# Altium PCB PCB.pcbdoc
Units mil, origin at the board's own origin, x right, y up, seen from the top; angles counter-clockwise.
Board outline 5096.34 x 3724.82 mil, 2 copper layers (Top Layer, Bottom Layer); 10 components, 40 nets, 79 pads, 2 vias.
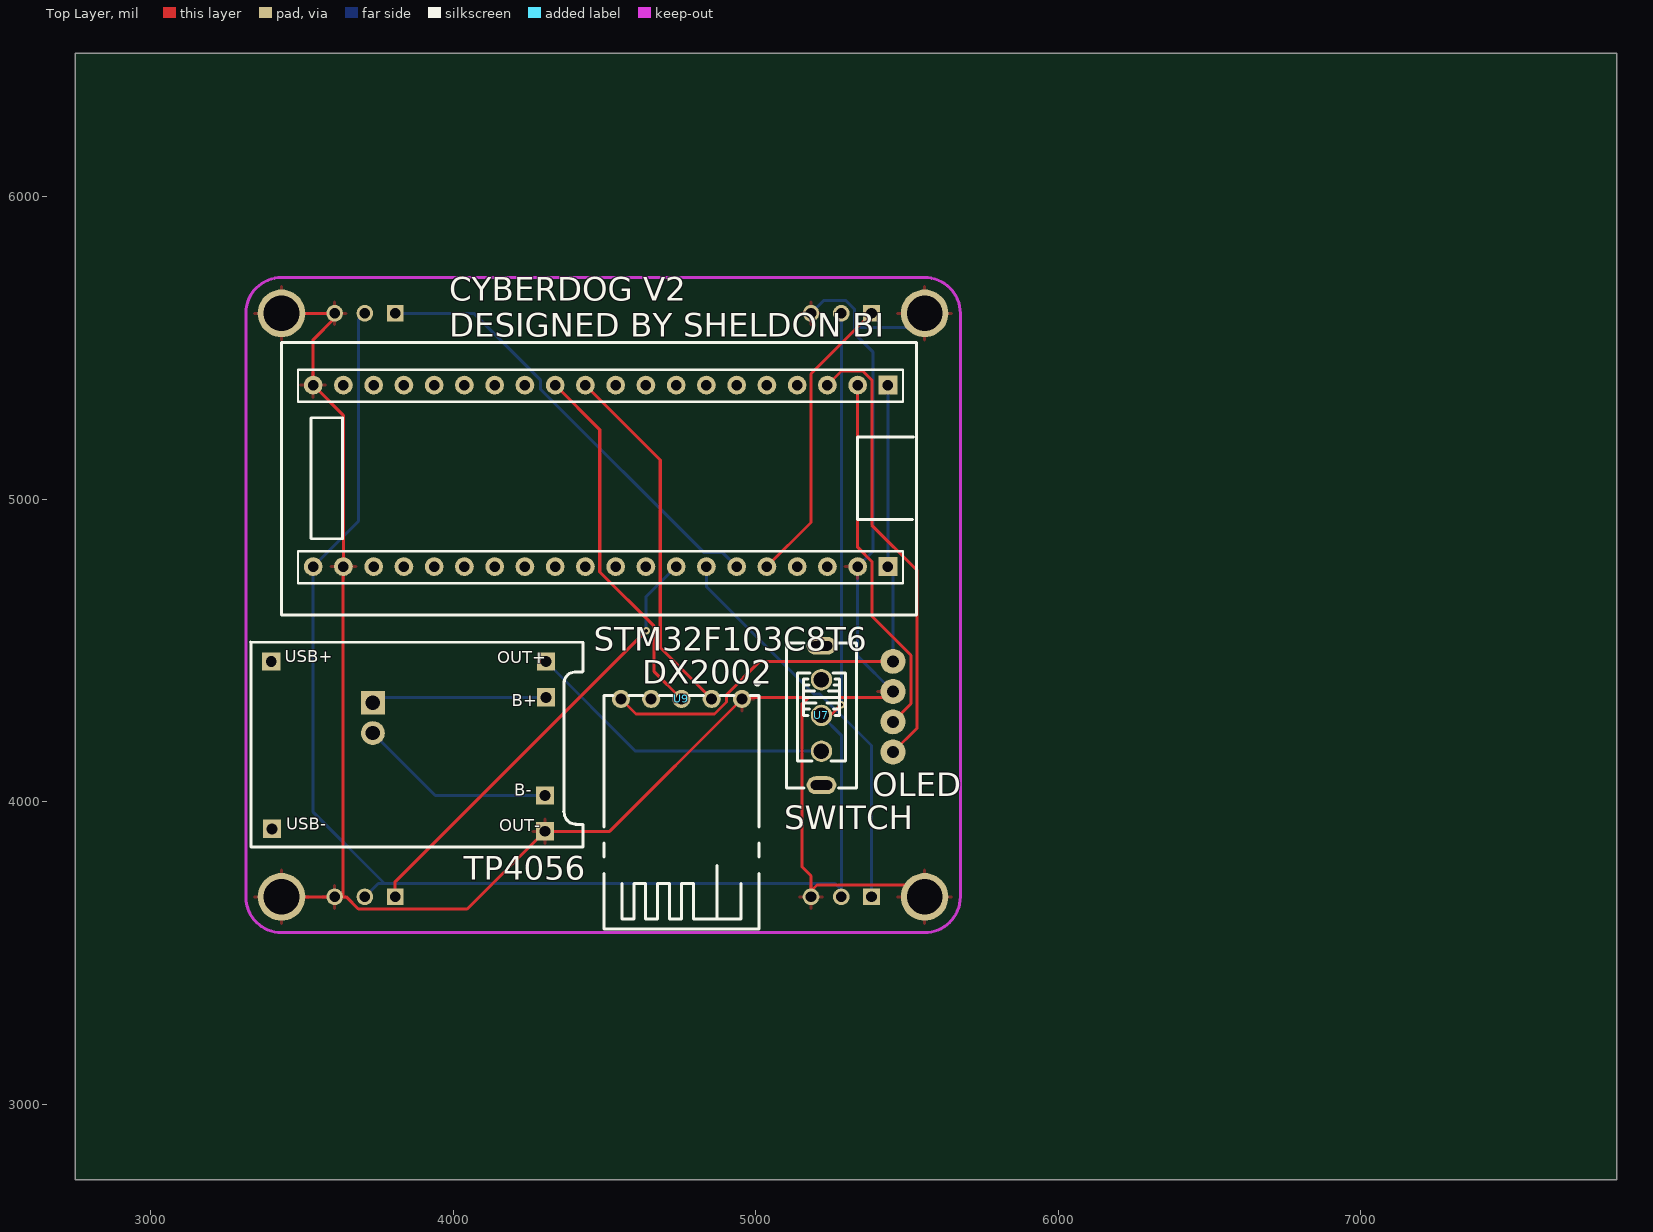
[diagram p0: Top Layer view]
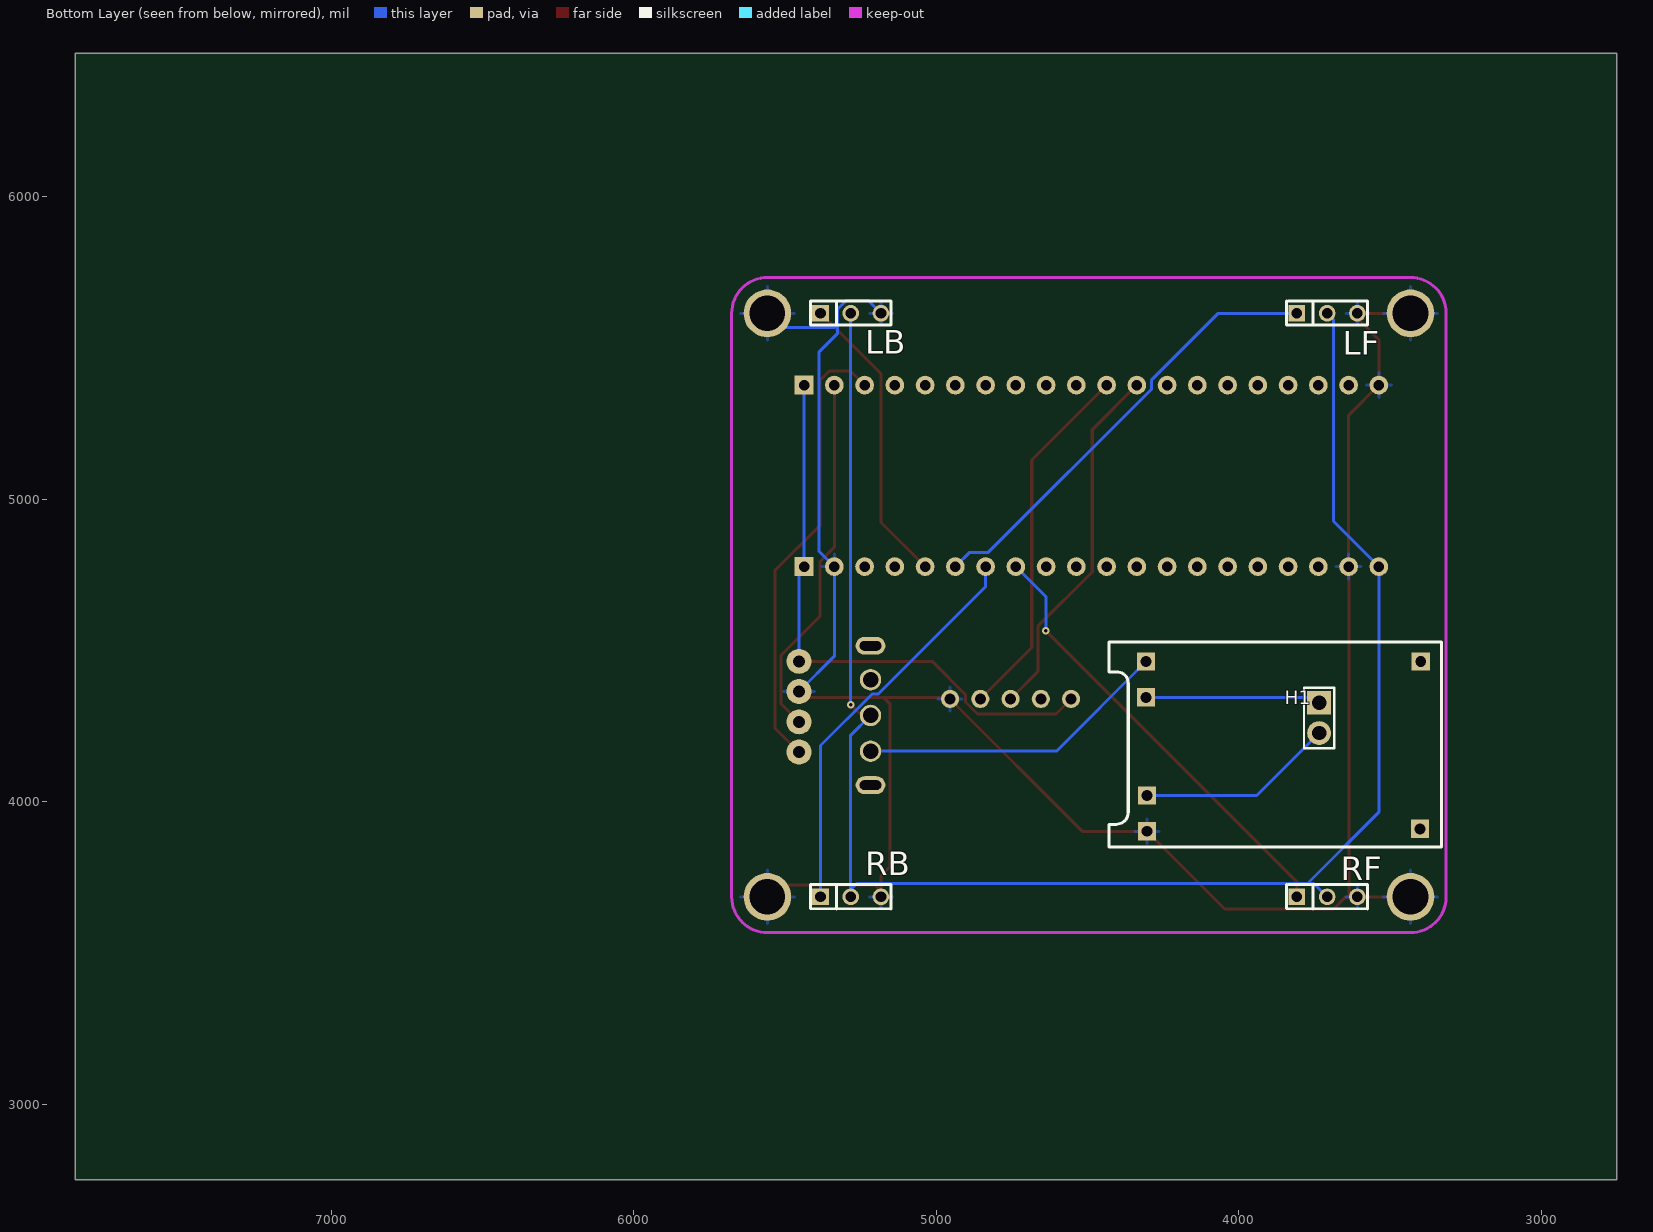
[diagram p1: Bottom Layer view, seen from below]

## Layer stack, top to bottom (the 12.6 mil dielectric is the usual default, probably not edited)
Top Layer: signal copper (thickness not stored)
Dielectric: dielectric 12.6, FR-4, Dk 4.8
Bottom Layer: signal copper (thickness not stored)

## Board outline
7846.34,2750 2750,2750 2750,6474.82 7846.34,6474.82

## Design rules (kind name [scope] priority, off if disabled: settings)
BoardOutlineClearance copperThickness1oz [All] p0: genericclearance=10 ignorepadtopadclearanceinfootprint=FALSE except(0: Arc-SplitContinuation Track-SplitContinuation SMDPad-SplitContinuation THPad-SplitContinuation Via-SplitContinuation Fill-SplitContinuation Poly-SplitContinuation Region-SplitContinuation Text-SplitContinuation; 6: SMDPad-CutoutEdge THPad-CutoutEdge Via-CutoutEdge Fill-CutoutEdge Region-CutoutEdge; 11.8: Track-OutlineEdge SMDPad-OutlineEdge THPad-OutlineEdge Via-OutlineEdge Fill-OutlineEdge Region-OutlineEdge Poly-OutlineEdge Text-OutlineEdge Track-CutoutEdge)
BoardOutlineClearance copperThickness2oz [All] p0: genericclearance=10 ignorepadtopadclearanceinfootprint=FALSE except(0: Arc-SplitContinuation Track-SplitContinuation SMDPad-SplitContinuation THPad-SplitContinuation Via-SplitContinuation Fill-SplitContinuation Poly-SplitContinuation Region-SplitContinuation Text-SplitContinuation; 6: SMDPad-CutoutEdge THPad-CutoutEdge Via-CutoutEdge Fill-CutoutEdge Region-CutoutEdge; 11.8: Track-OutlineEdge SMDPad-OutlineEdge THPad-OutlineEdge Via-OutlineEdge Fill-OutlineEdge Region-OutlineEdge Poly-OutlineEdge Text-OutlineEdge Track-CutoutEdge)
Clearance copperThickness1oz [(InNet('+5V') OR InNet('PA0') OR InNet('PA2') OR InNet('PA3') OR InNet('PA6') OR InNet('VCC') OR InNet('GND') OR InNet('PB9') OR InNet('PB8') OR InNet('PB7') OR InNet('PA15') OR InNet('BLUE_RX') OR InNet('PA8') OR InNet('K4') OR InNet('K3') OR InNet('K2') OR InNet('K1') OR InNet('BLUE_TX') OR InNet('BV-') OR InNet('PB4') OR InNet('PB3') OR InNet('B+5V') OR InNet('BV+') OR InNet('PA7') OR InNet('PB0') OR InNet('PB1') OR InNet('PB6') OR InNet('PB5') OR InNet('PA1') OR InNet('PA4') OR InNet('PA5') OR InNet('PB10') OR InNet('PB11') OR InNet('PA12') OR InNet('PA11') OR InNet('$1N16952') OR InNet('PB2') OR InNet('$1N16963') OR InNet('PA14') OR InNet('PA13'))] p1: gap=7 ignorepadtopadclearanceinfootprint=FALSE except(4: Track-Track; 6: Track-SMDPad SMDPad-SMDPad Track-THPad SMDPad-THPad THPad-THPad Track-Via SMDPad-Via THPad-Via Via-Via Track-Fill SMDPad-Fill THPad-Fill Via-Fill Fill-Fill SMDPad-Region THPad-Region Via-Region Fill-Region Region-Region Track-Poly SMDPad-Poly THPad-Poly Via-Poly Fill-Poly Poly-Poly Track-Text SMDPad-Text THPad-Text Via-Text Fill-Text Region-Text Poly-Text Text-Text Track-Hole SMDPad-Hole THPad-Hole Via-Hole Fill-Hole Region-Hole Poly-Hole Text-Hole; 11.8: Track-Region Region-Poly Track-Sheet SMDPad-Sheet THPad-Sheet Via-Sheet Fill-Sheet Region-Sheet Poly-Sheet Text-Sheet Sheet-Hole)
Clearance copperThickness2oz [All] p1: gap=7 ignorepadtopadclearanceinfootprint=FALSE except(6: Track-SMDPad SMDPad-SMDPad Track-THPad SMDPad-THPad THPad-THPad Track-Via SMDPad-Via THPad-Via Via-Via Track-Fill SMDPad-Fill THPad-Fill Via-Fill Fill-Fill SMDPad-Region THPad-Region Via-Region Fill-Region Region-Region Track-Poly SMDPad-Poly THPad-Poly Via-Poly Fill-Poly Poly-Poly Track-Text SMDPad-Text THPad-Text Via-Text Fill-Text Region-Text Poly-Text Text-Text Track-Hole SMDPad-Hole THPad-Hole Via-Hole Fill-Hole Region-Hole Poly-Hole Text-Hole; 8: Track-Track; 11.8: Track-Region Region-Poly Track-Sheet SMDPad-Sheet THPad-Sheet Via-Sheet Fill-Sheet Region-Sheet Poly-Sheet Text-Sheet Sheet-Hole)
DiffPairsRouting differentialPair [All] p1: maxuncoupledlength=10 minlimit=6 maxlimit=6 mostfreqgap=6 toplayer_minwidth=5 toplayer_prefwidth=10 toplayer_maxwidth=100 bottomlayer_minwidth=5 bottomlayer_prefwidth=10 bottomlayer_maxwidth=100
PasteMaskExpansion pasteMaskExpansion [All] p1: expansion=0
PlaneConnect innerPlane [All] p1: planeconnectstyle=Relief reliefexpansion=20 reliefentries=4 reliefconductorwidth=10 reliefairgap=10
PolygonConnect copperRegion [All] p1: connectstyle=Relief reliefentries=4 reliefconductorwidth=10 polygonreliefangle="90 Angle" airgapwidth=10
RoutingVias viaSize [All] p1: viastyle="Through Hole" holewidth=12.0078 minholewidth=11.811 maxholewidth=248.0314 width=24.0158 minwidth=19.685 maxwidth=393.7008
SolderMaskExpansion solderMaskExpansion [All] p1: useseparateexpansions=TRUE expansion=2 expansionbottom=2
Width copperThickness1oz [All] p1: maxlimit=100 minlimit=5 preferedwidth=10
Width copperThickness2oz [All] p1: maxlimit=100 minlimit=8 preferedwidth=10

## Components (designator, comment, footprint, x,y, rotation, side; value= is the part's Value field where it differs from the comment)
H1 "PZ254V-11-02P" HDR-TH_2P-P2.54-V-M 3734.15,4277.19 r270 bottom
LB "3pin插件排针" HDR-TH_3P-P2.54-V-M 5282.52,5614.94 r180 bottom
LF "3pin插件排针" HDR-TH_3P-P2.54-V-M 3707.72,5614.94 r180 bottom
OLED "OLED" "oled 1.3寸" 5453.36,4314.34 r270 top
RB "3pin插件排针" HDR-TH_3P-P2.54-V-M 5282.52,3685.81 r180 bottom
RF "3pin插件排针" HDR-TH_3P-P2.54-V-M 3707.72,3685.81 r180 bottom
STM32F103C8T6 "STM32F103C8T6最小系统" STM32F103C8T6 4501.65,5067.63 r0 top
TP4056 "TP4056模块" TP4056模块 4143.13,4035.91 r0 top
U7 "SS-12F44-G5" SW-TH_SS-12F44-G5_C2998807 5217.11,4285.49 r270 top
U9 "DX2002" realdx2002 4754.15,4065.19 r180 top

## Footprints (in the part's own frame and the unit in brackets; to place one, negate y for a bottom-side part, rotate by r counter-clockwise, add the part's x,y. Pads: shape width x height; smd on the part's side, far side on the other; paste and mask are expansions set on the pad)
HDR-TH_2P-P2.54-V-M [mm]
  rect 2x2 hole 1.2: 1(-1.27,0)
  round 2 hole 1.2: 2(1.27,0)
  silkscreen extent -2.54,-1.27 2.54,1.27
HDR-TH_3P-P2.54-V-M [mm]
  rect 1.4x1.4 hole 0.9: 1(-2.54,0)
  round 1.4 hole 0.9: 2(0,0) 3(2.54,0)
  silkscreen extent -3.39,-1 3.4,1.03
"oled 1.3寸" [mm]
  round 2.1 hole 1: 1(-3.81,0) 2(-1.27,0) 3(1.27,0) 4(3.81,0)
realdx2002 [mil]
  round 60 hole 36: 1(-200,-274.8) 2(-100,-274.8) 3(0,-274.8) 4(100,-274.8) 5(200,-274.8)
  silkscreen extent -257,-334 256,486
STM32F103C8T6 [mil]
  rect 62x62 hole 35: 1(935,310) 21(935,-290)
  round 62 hole 35: 2(835,310) 3(735,310) 4(635,310) 5(535,310) 7(335,310) 8(235,310) 9(135,310) 10(35,310) 11(-65,310) 12(-165,310) 13(-265,310) 14(-365,310) 15(-465,310) 16(-565,310) 17(-665,310) 18(-765,310) 18(-765,310) 19(-865,310) 20(-965,310) 22(835,-290) 23(735,-290) 24(635,-290) 25(535,-290) 26(435,-290) 27(335,-290) 28(235,-290) 29(135,-290) 30(35,-290) 31(-65,-290) 32(-165,-290) 33(-265,-290) 34(-365,-290) 35(-465,-290) 36(-565,-290) 37(-665,-290) 38(-765,-290) 39(-865,-290) 40(-965,-290)
  round 62 hole 35 copper offset -0.03,0: 6(435.07,309.92)
  silkscreen extent -1070,-450 1030,450
SW-TH_SS-12F44-G5_C2998807 [mm]
  round 1.8 hole 1.3: 1(-3,0) 2(0,0) 3(3,0)
  oval 1.5x2.5 hole 0.8 slot 1.8 at 90 deg: 4(5.85,0) 5(-5.85,0)
  silkscreen extent -6.1,-2.92 6.1,2.92
TP4056模块 [mil]
  rect 60x60 hole 36: 1(-741.92,-125.2) 2(-744.92,428) 3(159.68,-133.3) 4(163.18,427.7) 5(159.68,-15.2) 6(163.18,309.5)
  silkscreen extent -813,-185 285,492

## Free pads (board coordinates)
  round 157.48 hole 118.11: 1(3432.13,3685.81) 1(3432.13,5614.94) 1(5558.11,3685.81) 1(5558.11,5614.94)

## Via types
v1: diameter 24.02, hole 12.01, Top Layer to Bottom Layer, 2 vias

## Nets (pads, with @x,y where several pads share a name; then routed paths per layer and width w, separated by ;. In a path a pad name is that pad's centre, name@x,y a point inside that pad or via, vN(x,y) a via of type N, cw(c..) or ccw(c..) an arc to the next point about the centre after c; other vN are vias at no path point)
$1N16952: STM32F103C8T6.33
$1N16963: STM32F103C8T6.23
+5V: LB.2 LF.2 RB.2 RF.2 STM32F103C8T6.40 U7.2 | length 5655.8
  Top Layer w10: U7.2 5247.11,4285.49 v1(5282.52,4320.9)
  Bottom Layer w10: RF.2 3751.98,3730.07 3772.52,3730.07 ; LF.2 3686.65,5593.87 3686.65,4927.63 STM32F103C8T6.40 3536.65,3965.95 3772.52,3730.07 ; U7.2 5282.52,4220.07 RB.2@5282.52,3710.07 ; RB.2 RB.2@5282.52,3710.07 ; v1(5282.52,4320.9) LB.2 ; 3772.52,3730.07 5262.52,3730.07 RB.2@5282.52,3710.07
B+5V: TP4056.4 U7.3 | length 1033.5
  Bottom Layer w10: TP4056.4 4602.54,4167.38 U7.3
BLUE_RX: STM32F103C8T6.11 U9.2 | length 1210.6
  Top Layer w10: STM32F103C8T6.11 4684.15,5130.12 4684.15,4509.99 U9.2
BLUE_TX: STM32F103C8T6.12 U9.3 | length 1210.6
  Top Layer w10: STM32F103C8T6.12 4484.15,5230.12 4484.15,4759.99 4664.15,4579.99 4664.15,4429.99 U9.3
BV+: H1.1 TP4056.6 | length 579.7
  Bottom Layer w10: H1.1 3752.37,4345.41 TP4056.6
BV-: H1.2 TP4056.5 | length 654.2
  Bottom Layer w10: H1.2 3940.63,4020.71 TP4056.5
GND: LB.3 LF.3 OLED.2 pad.1 RB.3 RF.3 STM32F103C8T6.20 STM32F103C8T6.22 STM32F103C8T6.39 TP4056.3 U9.1 | length 7376.4
  Top Layer w10: pad.1@3432.13,3685.81 RF.3 3636.01,3685.81 ; pad.1@3432.13,5614.94 3433.2,5613.87 LF.3@3606.65,5613.87 ; LF.3 LF.3@3606.65,5613.87 ; RB.3 RB.3@5182.52,3705.18 ; OLED.2 5433.36,4344.34 5173.36,4344.34 ; pad.1@5558.11,3685.81 5518.74,3725.18 5202.52,3725.18 RB.3@5182.52,3705.18 ; LF.3@3606.65,5613.87 3606.65,5597.63 3536.65,5527.63 STM32F103C8T6.20 3636.65,5277.63 STM32F103C8T6.39 3636.01,4776.99 3636.01,3685.81 ; 3636.01,3685.81 3646.01,3685.81 3686.01,3645.81 4046.01,3645.81 TP4056.3 4516.77,3902.61 U9.1 4958.49,4344.34 5173.36,4344.34 ; 5173.36,4344.34 5153.36,4324.34 5153.36,3784.34 5182.52,3755.18 RB.3@5182.52,3705.18
  Bottom Layer w10: LB.3 5225.2,5657.63 5296.65,5657.63 5326.65,5627.63 5326.65,5577.63 ; OLED.2 5336.65,4481.06 STM32F103C8T6.22 5386.65,4827.63 5386.65,5487.63 5326.65,5547.63 5326.65,5577.63 ; pad.1@5558.11,5614.94 5510.79,5567.63 5336.65,5567.63 5326.65,5577.63
K1: STM32F103C8T6.6
K2: STM32F103C8T6.7
K3: STM32F103C8T6.8
K4: STM32F103C8T6.9
PA0: STM32F103C8T6.32
PA1: STM32F103C8T6.31
PA2: STM32F103C8T6.37
PA3: STM32F103C8T6.38
PA4: STM32F103C8T6.30
PA5: STM32F103C8T6.29
PA6: RF.1 STM32F103C8T6.28 | length 1476.6
  Top Layer w10: RF.1 3807.72,3735.81 v1(4637.72,4565.81)
  Bottom Layer w10: v1(4637.72,4565.81) 4637.72,4678.7 STM32F103C8T6.28
PA7: RB.1 STM32F103C8T6.27 | length 1329.6
  Bottom Layer w10: STM32F103C8T6.27 4836.65,4711.68 5192.52,4355.81 5212.52,4355.81 5382.52,4185.81 RB.1
PA8: STM32F103C8T6.10
PA11: STM32F103C8T6.13
PA12: STM32F103C8T6.14
PA13: STM32F103C8T6.15
PA14: STM32F103C8T6.16
PA15: STM32F103C8T6.17
PB0: LF.1 STM32F103C8T6.26 | length 1493.3
  Bottom Layer w10: LF.1 4067.72,5614.94 4287.72,5394.94 4287.72,5364.94 4827.72,4824.94 4889.33,4824.94 STM32F103C8T6.26
PB1: LB.1 STM32F103C8T6.25 | length 980.6
  Top Layer w10: STM32F103C8T6.25 5182.52,4923.5 5182.52,5414.94 LB.1
PB2: STM32F103C8T6.24
PB3: STM32F103C8T6.18
PB4: STM32F103C8T6.19
PB5: STM32F103C8T6.36
PB6: STM32F103C8T6.35
PB7: STM32F103C8T6.34
PB8: OLED.3 STM32F103C8T6.2 | length 1211.3
  Top Layer w10: STM32F103C8T6.2 5336.65,4841.06 5383.36,4794.34 5383.36,4614.34 5513.36,4484.34 5513.36,4324.34 OLED.3
PB9: OLED.4 STM32F103C8T6.3 | length 1503.8
  Top Layer w10: STM32F103C8T6.3 5283.36,5424.34 5353.36,5424.34 5383.36,5394.34 5383.36,4914.34 5533.36,4764.34 5533.36,4244.34 OLED.4
PB10: STM32F103C8T6.4
PB11: STM32F103C8T6.5
VCC: OLED.1 STM32F103C8T6.1 STM32F103C8T6.21 U9.5 | length 1926.6
  Top Layer w10: U9.5 4604.15,4289.99 4863.36,4289.99 4903.36,4329.99 4903.36,4354.34 5013.36,4464.34 OLED.1
  Bottom Layer w10: STM32F103C8T6.1 STM32F103C8T6.21 5453.36,4760.91 OLED.1
pads on no net: TP4056.1 TP4056.2 U7.1 U7.4 U7.5 U9.4

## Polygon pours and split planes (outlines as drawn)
GND on Top Layer (solid, remove dead copper, pour order 0): 3004.34,6224.82 7592,6224.82 7592,3000 3004.34,3000
GND on Bottom Layer (solid, remove dead copper, pour order 2): 3000,6216.14 7596.34,6216.14 7596.34,3013.02 3000,3013.02

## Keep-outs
Board Outline Layer:
  lines w10: 3314.02,3685.81 ccw(c3432.13,3685.81) 3432.13,3567.7 5558.11,3567.7 ccw(c5558.11,3685.81) 5676.22,3685.81 5676.22,5614.94 ccw(c5558.11,5614.94) 5558.11,5733.05 3432.13,5733.05 ccw(c3432.13,5614.94) 3314.02,5614.94 3314.02,3685.81

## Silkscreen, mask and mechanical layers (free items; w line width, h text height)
Top Silkscreen Layer:
  text "CYBERDOG V2 / DESIGNED BY SHELDON BI" at 3986.91,5538.15 h78.74
  text "DX2002" at 4624.37,4390.01 h78.74
  text "SWITCH" at 5094.66,3909.68 h78.74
